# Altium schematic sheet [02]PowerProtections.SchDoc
size A4; SheetNumber: 2; SheetTotal: 5
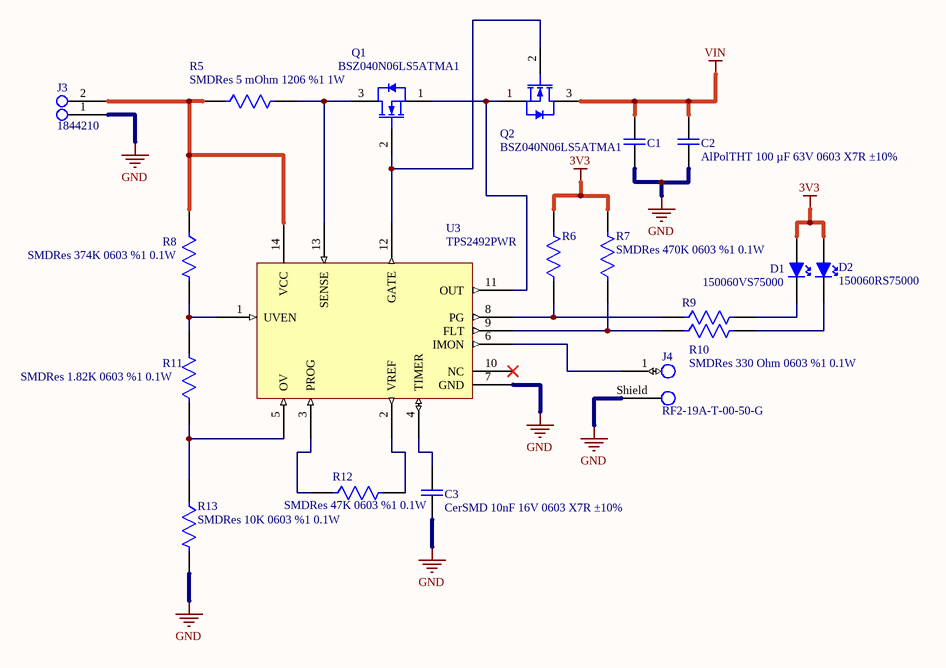
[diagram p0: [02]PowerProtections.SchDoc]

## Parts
C1  AlPolTHT 100 µF 63V 0603 X7R ±10%  [107AVG063MFBJ]  (value not drawn)
C2  AlPolTHT 100 µF 63V 0603 X7R ±10%  [107AVG063MFBJ]
C3  CerSMD 10nF 16V 0603 X7R ±10%  [CAPC1608X09N]
D1  150060VS75000  [LED1608X08N]
D2  150060RS75000  [LED1608X08N]
J3  1844210  [1844210]
J4  RF2-19A-T-00-50-G  [RF2-19A-T-00-50-G]
Q1  BSZ040N06LS5ATMA1  [PG-TSDSON-8-FL]
Q2  BSZ040N06LS5ATMA1  [PG-TSDSON-8-FL]
R5  SMDRes 5 mOhm 1206 %1 1W  [RESC3116X10N]
R6  SMDRes 470K 0603 %1 0.1W  [RESC1508X06N]  (value not drawn)
R7  SMDRes 470K 0603 %1 0.1W  [RESC1508X06N]
R8  SMDRes 374K 0603 %1 0.1W  [RESC1508X06N]
R9  MDRes 330 Ohm 0603 %1 0.1W  [RESC1508X06N]  (value not drawn)
R10  SMDRes 330 Ohm 0603 %1 0.1W  [RESC1508X06N]
R11  SMDRes 1.82K 0603 %1 0.1W  [RESC1508X06N]
R12  SMDRes 47K 0603 %1 0.1W  [RESC1508X06N]
R13  SMDRes 10K 0603 %1 0.1W  [RESC1508X06N]
U3  TPS2492PWR  [TSOP65P640X120-14L]

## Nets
3V3: D1.1(A) D2.1(A) R6.2 R7.2
GND: C1.2 C2.2 C3.2 J3.1 J4.Shield R13.2 U3.7(GND)
VIN: C1.1 C2.1 Q2.3(D)
NetC3_1: C3.1 U3.4(TIMER)
NetD1_2: D1.2(K) R9.2
NetD2_2: D2.2(K) R10.2
NetJ3_2: J3.2 R5.1 R8.1 U3.14(VCC)
NetJ4_1: J4.1 U3.6(IMON)
NetQ1_1: Q1.1(S) Q2.1(S) U3.11(OUT)
NetQ1_2: Q1.2(G) Q2.2(G) U3.12(GATE)
NetQ1_3: Q1.3(D) R5.2 U3.13(SENSE)
NetR6_1: R6.1 R9.1 U3.8(PG)
NetR7_1: R7.1 R10.1 U3.9(FLT)
NetR8_2: R8.2 R11.2 U3.1(UVEN)
NetR11_1: R11.1 R13.1 U3.5(OV)
NetR12_1: R12.1 U3.3(PROG)
NetR12_2: R12.2 U3.2(VREF)

Not connected (* = marked no-connect by the designer): U3 10(NC)*

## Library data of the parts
C1 C2 = CMP-00002-4: Ceramic Capacitor SMD 100 µF 63V 0603 X7R ±10%; Manufacturer: Cornell Dubilier Knowles
C3 = CMP-00001-3: Ceramic Capacitor SMD  10nF 16V 0603 X7R ±10%; Manufacturer Number: CL10B103KO8WPNC; Manufacturer: Samsung Electro-Mechanics
D1 = CMP-00028-1: GREEN LED 0603
D2 = CMP-00024-1: RED LED 0603
J3 = CMP-00023-1: 12A 2-Pos, Right Angle
J4 = CMP-00025-2: Rf Sma Connector
Q1 Q2 = CMP-00004-1: N-MOS 60V 17A (Ta) 101A (Tc)
R5 = CMP-00007-2: 5 mOhms ±1% 1W Chip Resistor 1206 (3216 Metric) Automotive AEC-Q200, Current Sense, Moisture Resistant Metal Foil; Manufacturer Number: CSRF1206FT5L00; Manufacturer: Stackpole Electronics Inc
R6 R7 = CMP-00006-1: Res Thick Film 0603 470K Ohm 1% 0.1W(1/10W) ±100ppm/C Pad SMD T/R Automotive AEC-Q200; Manufacturer: Stackpole Electronics Inc; Manufacturer Number: RMCF0603FT470K
R8 = CMP-00005-2: Res Thick Film 0603 374K Ohm 1% 0.1W(1/10W) ±100ppm/C Pad SMD T/R Automotive AEC-Q200; Manufacturer: Stackpole Electronics Inc; Manufacturer Number: RMCF0603FT374K
R9 R10 = CMP-00027-1: Res Thick Film 0603 33 kOhm Ohm 1% 0.1W(1/10W) ±100ppm/C Pad SMD T/R Automotive AEC-Q200; Manufacturer Number: RMCF0603FT330R; Manufacturer: Stackpole Electronics Inc
R11 = CMP-00003-2: Res Thick Film 0603 1.82K Ohm 1% 0.1W(1/10W) ±100ppm/C Pad SMD T/R Automotive AEC-Q200; Manufacturer: Stackpole Electronics Inc; Manufacturer Number: RMCF0603FT1K82
R12 = CMP-00008-1: Res Thick Film 0603 47K Ohm 1% 0.1W(1/10W) ±100ppm/C Pad SMD T/R Automotive AEC-Q200; Manufacturer Number: RMCF0603FT47K0; Manufacturer: Stackpole Electronics Inc
R13 = CMP-00001-1-1: Res Thick Film 0603 10K Ohm 1% 0.1W(1/10W) ±100ppm/C Pad SMD T/R Automotive AEC-Q200; Manufacturer Number: RMCF0603FT10K0; Manufacturer: Stackpole Electronics Inc
U3 = CMP-00000-2: eFuses - External MOSFETs - 9V-80V; Manufacturer: Texas Instruments; Temperature Rating: -40°C up to 125°C; Voltage Rating: 9V up to 80V; Internal Switch(s): No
